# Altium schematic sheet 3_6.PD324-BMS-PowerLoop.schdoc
size 848 x 601 mm; Symbol: Drawing-Symbol_A4; Device: Drawing-Symbol_A4; Company: 嘉立创EDA; Version: V1.0; Page Size: A4; @Project Name: PD324; @Page Count: 4; @Update Date: 2025-05-06; @Create Date: 2025-05-03; @Schematic Name: Schematic1; @Page No: 3; @Page Name: 6.PD324-BMS-PowerLoop; @Create Time: 10:51:21; @Update Time: 08:47:22; Width: 3304; Height: 2338; Region Start: 1; X Region Count: 6; Y Region Count: 4; Blade Width: 10; Title Block Position: 3; @Board Name: Board1
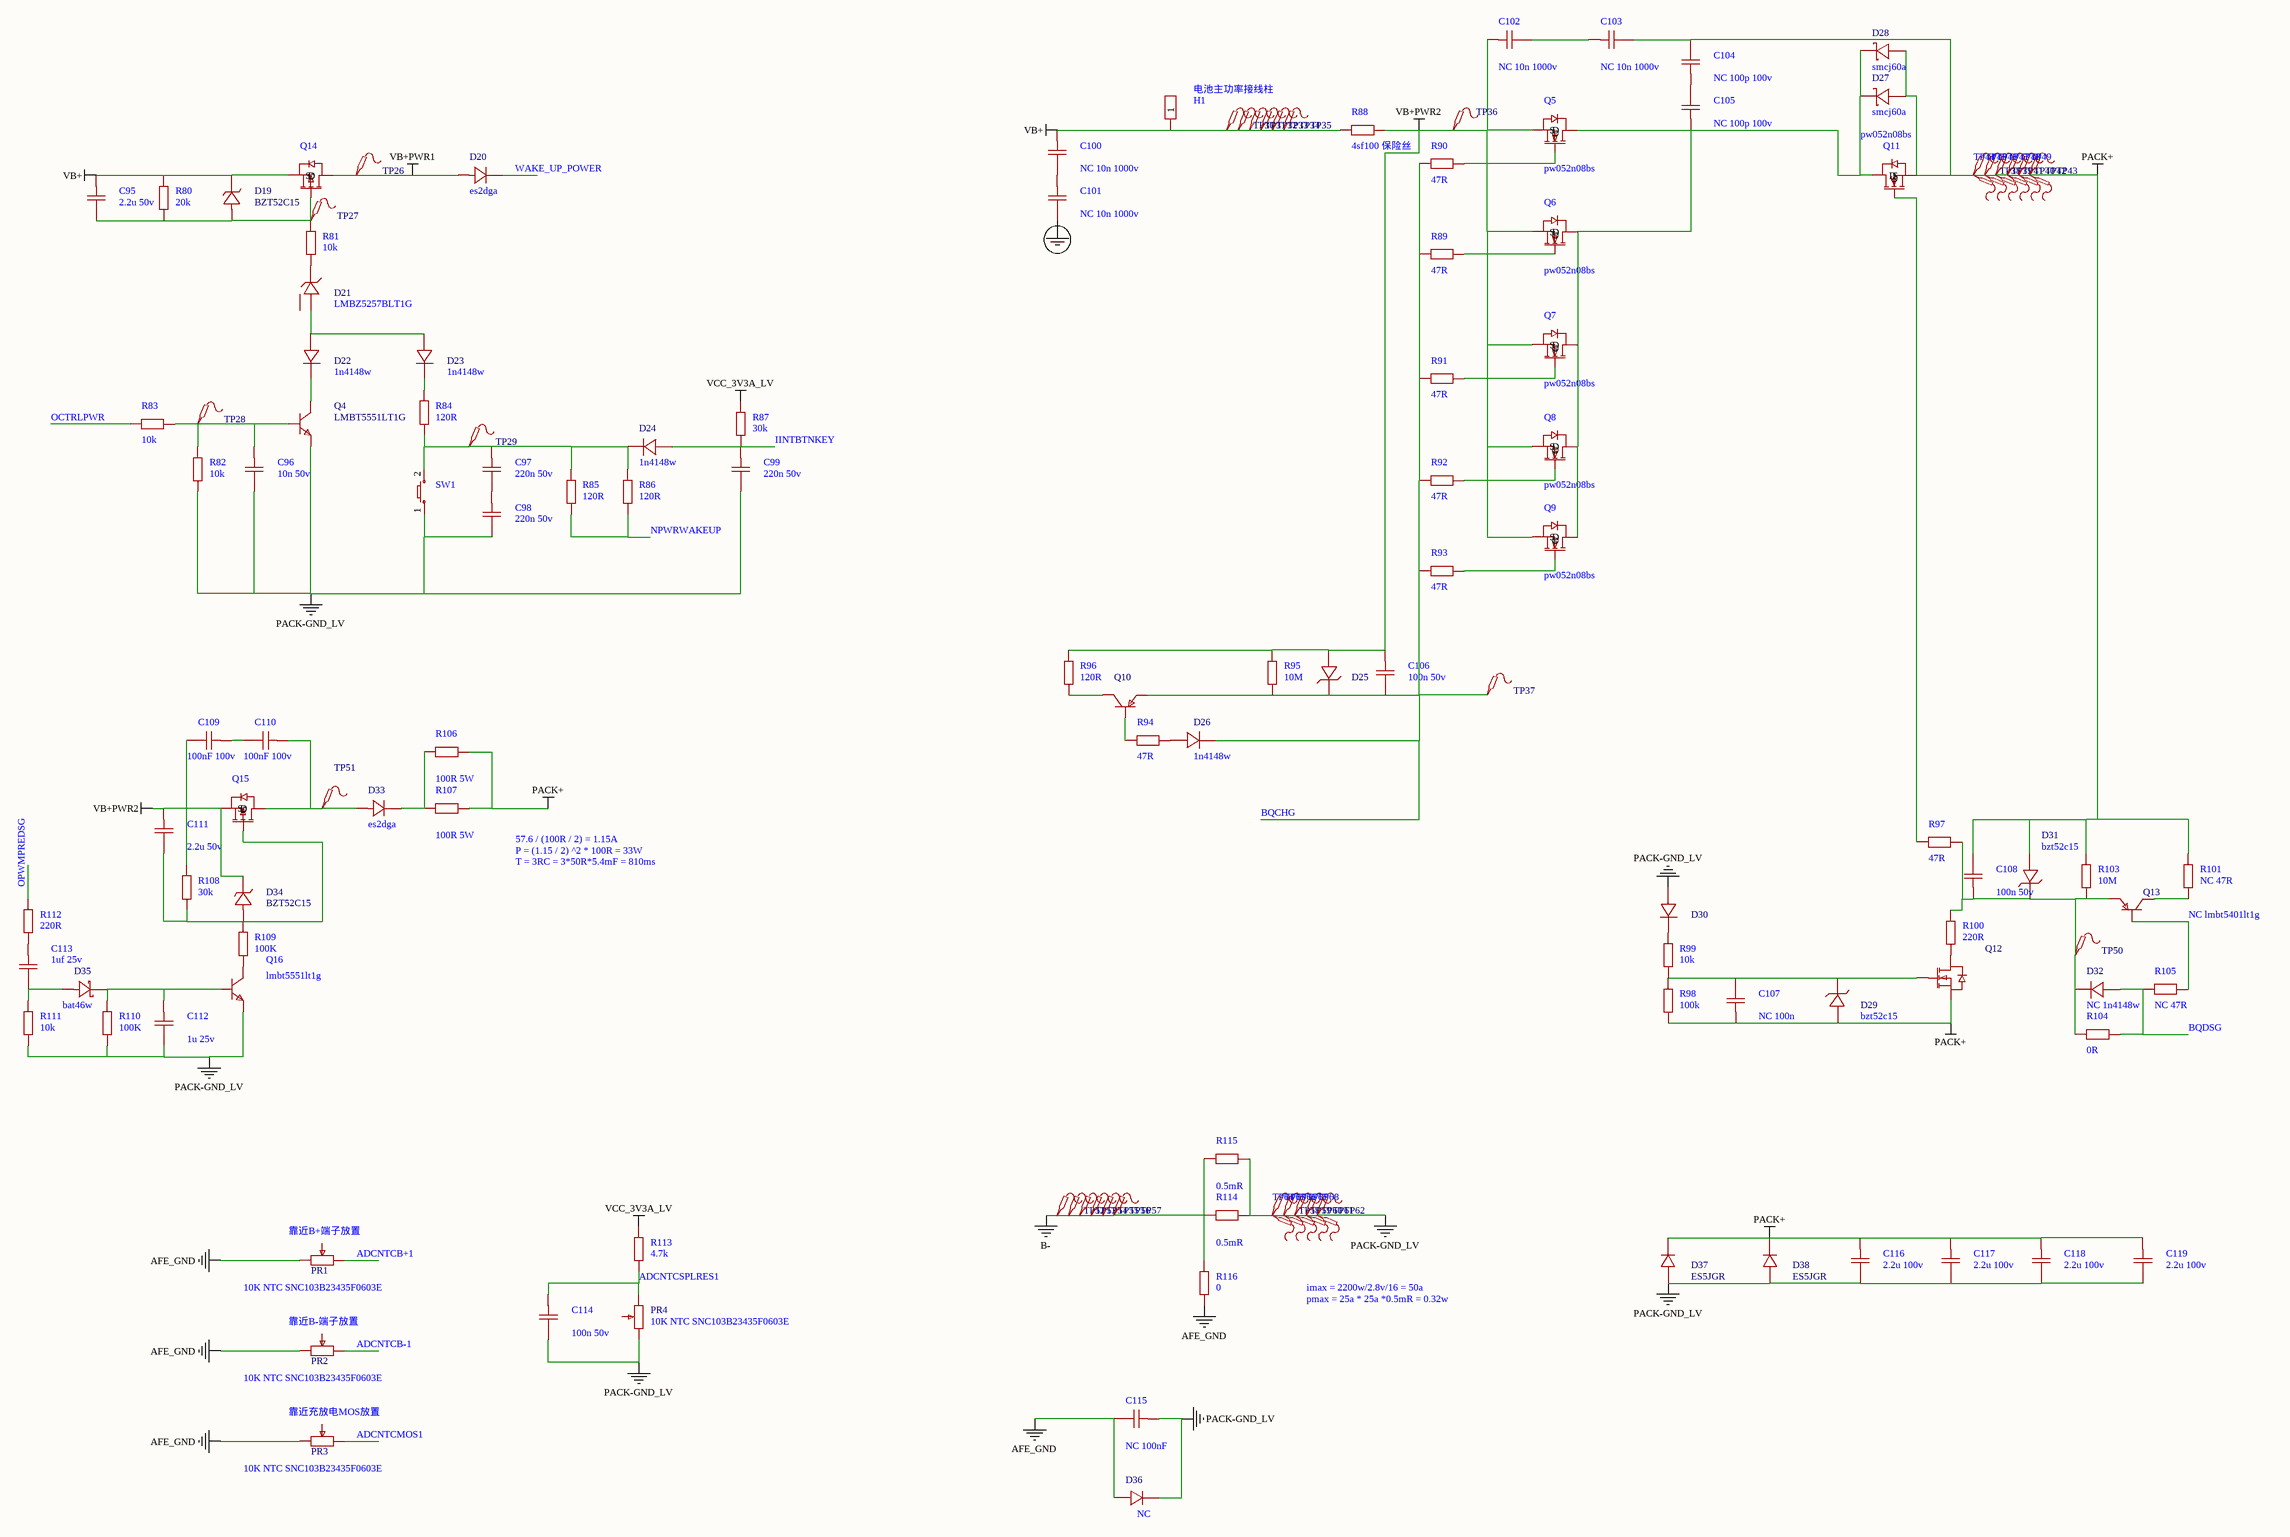
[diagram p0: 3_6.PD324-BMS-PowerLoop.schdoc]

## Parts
C95  2.2u 50v  [C0603]
C96  10n 50v  [C0603]
C97  220n 50v  [C0603]
C98  220n 50v  [C0603]
C99  220n 50v  [C0603]
C100  NC 10n 1000v  [C1206]
C101  NC 10n 1000v  [C1206]
C102  NC 10n 1000v  [C1206]
C103  NC 10n 1000v  [C1206]
C104  NC 100p 100v  [C1206]
C105  NC 100p 100v  [C1206]
C106  100n 50v  [C0603]
C107  NC 100n  [C1206]
C108  100n 50v  [C1206]
C109  100nF 100v  [C1206]
C110  100nF 100v  [C1206]
C111  2.2u 50v  [C1206]
C112  1u 25v  [C1206]
C113  1uf 25v  [C1206]
C114  100n 50v  [C1206]
C115  NC 100nF  [C1206]
C116  2.2u 100v  [C1206]
C117  2.2u 100v  [C1206]
C118  2.2u 100v  [C1206]
C119  2.2u 100v  [C1206]
D19  BZT52C15  [SOD-123_L2.7-W1.7-LS3.8-RD]
D20  es2dga  [SMA_L4.5-W2.6-LS5.1-RD]
D21  LMBZ5257BLT1G  [SOT-23_L2.9-W1.3-P1.90-LS2.4-BR]
D22  1n4148w  [SOD-123_L2.8-W1.8-LS3.7-RD]
D23  1n4148w  [SOD-123_L2.8-W1.8-LS3.7-RD]
D24  1n4148w  [SOD-123_L2.8-W1.8-LS3.7-RD]
D25  BZT52C15-7-F  [SOD-123F_L2.8-W1.8-LS3.7-RD]  (value not drawn)
D26  1n4148w  [SOD-123_L2.8-W1.8-LS3.7-RD]
D27  smcj60a  [SMC_L6.9-W5.9-LS7.9-RD]
D28  smcj60a  [SMC_L6.9-W5.9-LS7.9-RD]
D29  bzt52c15  [SOD-123F_L2.8-W1.8-LS3.7-RD]
D30  1N4148W-E3-08  [SOD-123_L2.8-W1.8-LS3.7-RD]  (value not drawn)
D31  bzt52c15  [SOD-123F_L2.8-W1.8-LS3.7-RD]
D32  NC 1n4148w  [SOD-123_L2.8-W1.8-LS3.7-RD]
D33  es2dga  [SMA_L4.3-W2.6-LS5.2-RD]
D34  BZT52C15  [SOD-123_L2.7-W1.7-LS3.8-RD]
D35  bat46w  [SOD-323_L1.8-W1.3-LS2.5-RD]
D36  NC  [SOD-123_L2.7-W1.6-LS3.7-RD]
D37  ES5JGR  [SMC_L6.9-W5.9-LS7.9-RD]
D38  ES5JGR  [SMC_L6.9-W5.9-LS7.9-RD]
H1  电池主功率接线柱  [HDR-TH_1P-V-M_XKB_X4611WV-01I-C28D40]
PR1  10K NTC SNC103B23435F0603E  [R_3386P]
PR2  10K NTC SNC103B23435F0603E  [R_3386P]
PR3  10K NTC SNC103B23435F0603E  [R_3386P]
PR4  10K NTC SNC103B23435F0603E  [R_3386P]
Q4  LMBT5551LT1G  [SOT-23-3_L2.9-W1.3-P1.90-LS2.4-BR]
Q5  pw052n08bs  [IRF640_TO-220]
Q6  pw052n08bs  [IRF640_TO-220]
Q7  pw052n08bs  [IRF640_TO-220]
Q8  pw052n08bs  [IRF640_TO-220]
Q9  pw052n08bs  [IRF640_TO-220]
Q10  LMBT5401LT1G  [SOT-23-3_L2.9-W1.3-P1.90-LS2.4-BR]  (value not drawn)
Q11  pw052n08bs  [IRF640_TO-220]
Q12  YJL3400A  [SOT-23-3_L2.9-W1.3-P1.90-LS2.4-BR]  (value not drawn)
Q13  NC lmbt5401lt1g  [SOT-23-3_L2.9-W1.3-P1.90-LS2.4-BR]
Q14  (no value)  [AO3401A_SOT-23-3]
Q15  (no value)  [AO3401A_SOT-23-3]
Q16  lmbt5551lt1g  [S8050_SOT-23]
R80  20k  [R0603]
R81  10k  [R0603]
R82  10k  [R0603]
R83  10k  [R0603]
R84  120R  [R0603]
R85  120R  [R0603]
R86  120R  [R0603]
R87  30k  [R0603]
R88  4sf100 保险丝  [R0603]
R89  47R  [R0603]
R90  47R  [R0603]
R91  47R  [R0603]
R92  47R  [R0603]
R93  47R  [R0603]
R94  47R  [R0603]
R95  10M  [R0603]
R96  120R  [R0603]
R97  47R  [R0603]
R98  100k  [R0603]
R99  10k  [R0603]
R100  220R  [R0603]
R101  NC 47R  [R1206]
R103  10M  [R0603]
R104  0R  [R0603]
R105  NC 47R  [R0603]
R106  100R 5W  [R0603]
R107  100R 5W  [R0603]
R108  30k  [R0603]
R109  100K  [R0603]
R110  100K  [R0603]
R111  10k  [R0603]
R112  220R  [R0603]
R113  4.7k  [R0603]
R114  0.5mR  [R0603]
R115  0.5mR  [R0603]
R116  0  [R0603]
SW1  (no value)  [Key_SMD_3x4x2]
TP26  (no value)  [Test-Point-0.5mm]
TP27  (no value)  [Test-Point-0.5mm]
TP28  (no value)  [Test-Point-0.5mm]
TP29  (no value)  [Test-Point-0.5mm]
TP30  (no value)  [Test-Point-0.5mm]
TP31  (no value)  [Test-Point-0.5mm]
TP32  (no value)  [Test-Point-0.5mm]
TP33  (no value)  [Test-Point-0.5mm]
TP34  (no value)  [Test-Point-0.5mm]
TP35  (no value)  [Test-Point-0.5mm]
TP36  (no value)  [Test-Point-0.5mm]
TP37  (no value)  [Test-Point-0.5mm]
TP38  (no value)  [Test-Point-0.5mm]
TP39  (no value)  [Test-Point-0.5mm]
TP40  (no value)  [Test-Point-0.5mm]
TP41  (no value)  [Test-Point-0.5mm]
TP42  (no value)  [Test-Point-0.5mm]
TP43  (no value)  [Test-Point-0.5mm]
TP44  (no value)  [Test-Point-0.5mm]
TP45  (no value)  [Test-Point-0.5mm]
TP46  (no value)  [Test-Point-0.5mm]
TP47  (no value)  [Test-Point-0.5mm]
TP48  (no value)  [Test-Point-0.5mm]
TP49  (no value)  [Test-Point-0.5mm]
TP50  (no value)  [Test-Point-0.5mm]
TP51  (no value)  [Test-Point-0.5mm]
TP52  (no value)  [Test-Point-0.5mm]
TP53  (no value)  [Test-Point-0.5mm]
TP54  (no value)  [Test-Point-0.5mm]
TP55  (no value)  [Test-Point-0.5mm]
TP56  (no value)  [Test-Point-0.5mm]
TP57  (no value)  [Test-Point-0.5mm]
TP58  (no value)  [Test-Point-0.5mm]
TP59  (no value)  [Test-Point-0.5mm]
TP60  (no value)  [Test-Point-0.5mm]
TP61  (no value)  [Test-Point-0.5mm]
TP62  (no value)  [Test-Point-0.5mm]
TP64  (no value)  [Test-Point-0.5mm]
TP65  (no value)  [Test-Point-0.5mm]
TP66  (no value)  [Test-Point-0.5mm]
TP67  (no value)  [Test-Point-0.5mm]
TP68  (no value)  [Test-Point-0.5mm]

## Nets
AFE_GND: C115.1 D36.2 PR1.3 PR2.3 PR3.3 R116.1
B-: R114.1 R115.1 R116.2 TP52.1 TP53.1 TP54.1 TP55.1 TP56.1 TP57.1
PACK+: C103.1 C104.1 C107.2 C108.1 C116.2 C117.2 C118.2 C119.2 D27.2(A) D28.2(A) D29.2(A) D31.2(A) D37.1 D38.1 Q11.3(S) Q12.2(S) R98.2 R101.2 R103.1 R106.2 R107.2 TP38.1 TP39.1 TP40.1 TP41.1 TP42.1 TP43.1 TP44.1 TP45.1 TP46.1 TP47.1 TP48.1 TP49.1
PACK-GND_LV: C96.1 C98.1 C99.1 C112.1 C114.1 C115.2 C116.1 C117.1 C118.1 C119.1 D30.2(A) D36.1 D37.2 D38.2 PR4.3 Q4.2(E) Q16.2 R82.1 R110.1 R111.1 R114.2 R115.2 SW1.1 TP58.1 TP59.1 TP60.1 TP61.1 TP62.1 TP64.1 TP65.1 TP66.1 TP67.1 TP68.1
PGND: C101.1
VB+: C95.2 C100.2 D19.1(K) H1.1 Q14.2(S) R80.2 R88.2 TP30.1 TP31.1 TP32.1 TP33.1 TP34.1 TP35.1
VB+PWR1: D20.2(A) Q14.3(D) TP26.1
VB+PWR2: C102.2 C106.2 C109.1 C111.2 D25.2(A) D34.1(K) Q5.3(S) Q6.3(S) Q7.3(S) Q8.3(S) Q9.3(S) Q15.2(S) R88.1 R95.1 R96.1 R108.2 TP36.1
VCC_3V3A_LV: R87.2 R113.2
ADCNTCB+1: PR1.1
ADCNTCB-1: PR2.1
ADCNTCMOS1: PR3.1
ADCNTCSPLRES1: C114.2 PR4.1 R113.1
BQCHG: C106.1 D25.1(K) D26.1(K) Q10.2(E) R89.2 R90.2 R91.2 R92.2 R93.2 R95.2 TP37.1
BQDSG: D32.2(A) R104.2 R105.1
IINTBTNKEY: C99.2 D24.2(A) R87.1
NPWRWAKEUP: R85.1 R86.1
OCTRLPWR: R83.2
OPWMPREDSG: R112.2
WAKE_UP_POWER: D20.1(K)
NetC95_1: C95.1 D19.2(A) Q14.1(G) R80.1 R81.2 TP27.1
NetC96_2: C96.2 Q4.1(B) R82.2 R83.1 TP28.1
NetC97_1: C97.1 C98.2
NetC97_2: C97.2 D24.1(K) R84.1 R85.2 R86.2 SW1.2 TP29.1
NetC100_1: C100.1 C101.2
NetC102_1: C102.1 C103.2
NetC104_2: C104.2 C105.1
NetC105_2: C105.2 D27.1(K) D28.1(K) Q5.2(D) Q6.2(D) Q7.2(D) Q8.2(D) Q9.2(D) Q11.2(D)
NetC107_1: C107.1 D29.1(K) Q12.1(G) R98.1 R99.2
NetC108_2: C108.2 D31.1(K) D32.1(K) Q13.2(E) R97.1 R100.1 R103.2 R104.1 TP50.1
NetC109_2: C109.2 C110.1
NetC110_2: C110.2 D33.2(A) Q15.3(D) TP51.1
NetC111_1: C111.1 D34.2(A) Q15.1(G) R108.1 R109.2
NetC112_2: C112.2 D35.1(K) Q16.1 R110.2
NetC113_1: C113.1 D35.2(A) R111.2
NetC113_2: C113.2 R112.1
NetD21_1: D21.1(A) D22.2(A) D23.2(A)
NetD21_3: D21.3(C) R81.1
NetD22_1: D22.1(K) Q4.3(C)
NetD23_1: D23.1(K) R84.2
NetD26_2: D26.2(A) R94.1
NetD30_1: D30.1(K) R99.1
NetD33_1: D33.1(K) R106.1 R107.1
NetQ5_1: Q5.1(G) R90.1
NetQ6_1: Q6.1(G) R89.1
NetQ7_1: Q7.1(G) R91.1
NetQ8_1: Q8.1(G) R92.1
NetQ9_1: Q9.1(G) R93.1
NetQ10_1: Q10.1(B) R94.2
NetQ10_3: Q10.3(C) R96.2
NetQ11_1: Q11.1(G) R97.2
NetQ12_3: Q12.3(D) R100.2
NetQ13_1: Q13.1(B) R105.2
NetQ13_3: Q13.3(C) R101.1
NetQ16_3: Q16.3 R109.1

Not connected (* = marked no-connect by the designer): D21 2; PR1 2; PR2 2; PR3 2; PR4 2

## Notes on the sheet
- 57.6 / (100R / 2) = 1.15A
  P = (1.15 / 2) ^2 * 100R = 33W
  T = 3RC = 3*50R*5.4mF = 810ms
- (near PR1) 靠近B+端子放置
- (near PR2) 靠近B-端子放置
- imax = 2200w/2.8v/16 = 50a
- pmax = 25a * 25a *0.5mR = 0.32w
- (near PR3) 靠近充放电MOS放置

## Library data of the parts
C95-C99 C106 = CAP_0603: Symbol: CapAcitance; Convert to PCB: yes
C100-C105 C107-C119 = CAP_1206: Symbol: CapAcitance; Convert to PCB: yes
D19 D34 = BZT52C15: Manufacturer: TWGMC(台湾迪嘉); Symbol: BZT52C15_C727006; Add into BOM: yes; Diode Configuration: 独立式; Zener Voltage (Nom): 15V; Reverse Leakage Current (Ir): 100nA@10.5V; Zener Voltage (Range): 13.8V~15.6V; Power Dissipation: 500mW; Zener Impedance (Zzt): 30Ω
D20 = ES2DA_C2944268: Manufacturer: RUILON(瑞隆源); Manufacturer Part: ES2DA; Add into BOM: yes; Diode Configuration: 独立式; Voltage - Forward(Vf@If): 950mV@2A; Voltage - DC Reverse(Vr): 200V; Current - Rectified: 2A; Reverse Leakage Current (Ir): 5uA@200V; Reverse Recovery Time (trr): 35ns
D21 = LMBZ5257BLT1G: Manufacturer: LRC(乐山无线电); Add into BOM: yes; Diode Configuration: 独立式; Zener Voltage(Nom): 33V; Zener Voltage(Range): 31.35V~34.65V; Pd - Power Dissipation: 225mW; Impedance(Zzt): 58Ω
D22-D24 D26 D30 D32 = 1N4148W-E3-08: Manufacturer: VISHAY(威世); Add into BOM: yes; Forward Voltage (Vf@If): 1.2V@100mA; Reverse Voltage (Vr): 75V; Rectified Current: 150mA; Reverse Leakage Current: 100uA@100V; Reverse Recovery Time (trr): 4ns
D25 D29 D31 = BZT52C15-7-F: Manufacturer: DIODES(美台); Add into BOM: yes; Diode Configuration: 独立式; Zener Voltage (Nom): 15V; Reverse Leakage Current (Ir): 100nA@10.5V; Zener Voltage (Range): 13.8V~15.6V; Power Dissipation: 500mW; Zener Impedance (Zzt): 30Ω
D27 D28 = SMCJ60A-E3/57T: Manufacturer: VISHAY(威世); Add into BOM: yes; polarity: 单向; Reverse Stand-Off Voltage (Vrwm): 60V; Maximum Clamping Voltage: 96.8V; Peak Pulse Current (Ipp)@10/1000us: 15.5A; Peak Pulse Power Dissipation (Ppp)@10/1000us: 1.5kW; Breakdown Voltage: 66.7V; Type: TVS
D33 = ES2DA: Manufacturer: YANGJIE(扬杰); Add into BOM: yes; Diode Configuration: 独立式; Forward Voltage (Vf@If): 950mV@2A; Reverse Voltage (Vr): 200V; Rectified Current: 2A; Reverse Leakage Current: 5uA@200V; Reverse Recovery Time (trr): 35ns
D35 = BAT46WS: Manufacturer: FUXINSEMI(富芯森美); Symbol: BAT46WS_C908225; Add into BOM: yes; Forward Voltage (Vf@If): 1V@250mA; Reverse Voltage (Vr): 100V; Average Rectified Current (Io): 150mA; Reverse Leakage Current (Ir): 2uA@75V
D36 = BAT46W: Manufacturer: DIOTEC(德欧泰克); Symbol: BAT46W_C212799; Add into BOM: yes; Forward Voltage (Vf@If): 450mV@10mA; Reverse Voltage (Vr): 100V; Rectified Current: 150mA; Reverse Leakage Current (Ir): 5uA@75V
D37 D38 = ES5JGR: Manufacturer: PINGWEI(平伟); Add into BOM: yes; Forward Voltage (Vf@If): 1.7V@5A; Reverse Voltage (Vr): 600V; Rectified Current: 5A; Reverse Leakage Current: 5uA@600V; Reverse Recovery Time (trr): 35ns
H1 = HDR-M_2.54_1x1P: Symbol: HDR_1x1; Convert to PCB: yes
PR1-PR4 = R_3386P: Symbol: 3386P-1-103LF; Convert to PCB: yes
Q4 = LMBT5551LT1G: Manufacturer: LRC(乐山无线电); Add into BOM: yes; type: NPN; Current - Collector(Ic): 600mA; Collector - Emitter Voltage VCEO: 160V; Pd - Power Dissipation: 225mW; DC Current Gain: 80@10mA,5.0V; Current - Collector Cutoff: 50nA; Vce Saturation(VCE(sat)): 200mV
Q5-Q9 Q11 = IRF640_N: Symbol: IRF640NPBF_N; Add into BOM: yes
Q10 Q13 = LMBT5401LT1G: Manufacturer: LRC(乐山无线电); Add into BOM: yes; type: PNP; Current - Collector(Ic): 500mA; Collector - Emitter Voltage VCEO: 150V; Pd - Power Dissipation: 300mW; DC Current Gain: 50@10mA,5.0V; Transition frequency(fT): 300MHz; Current - Collector Cutoff: 50uA
Q12 = YJL3400A: Manufacturer: YANGJIE(扬杰); Add into BOM: yes; Type: 1个N沟道; Drain Source Voltage (Vdss): 30V; Continuous Drain Current (Id): 5.6A; Drain Source On Resistance (RDS(on)@Vgs,Id): 51mΩ@2.5V,3.0A; Power Dissipation (Pd): 1.2W; Gate Threshold Voltage (Vgs(th)@Id): 650mV@250uA; Total Gate Charge (Qg@Vgs): 4.8nC@4.5V; Input Capacitance (Ciss@Vds): 535pF@15V; Reverse Transfer Capacitance (Crss@Vds): 36pF@15V
Q14 Q15 = AO3401A_P: Symbol: P_MOS; Add into BOM: yes
Q16 = S8050_SOT_NPN: Symbol: NPN; Convert to PCB: yes
R80-R100 R103-R116 = Res_0603: Symbol: 电阻; Convert to PCB: yes
R101 = Res_1206: Symbol: 电阻; Add into BOM: yes
SW1 = Key_SMD_3x4x2: Symbol: 轻触按键x2; Convert to PCB: yes
TP26-TP62 TP64-TP68 = Test-Point: Add into BOM: yes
